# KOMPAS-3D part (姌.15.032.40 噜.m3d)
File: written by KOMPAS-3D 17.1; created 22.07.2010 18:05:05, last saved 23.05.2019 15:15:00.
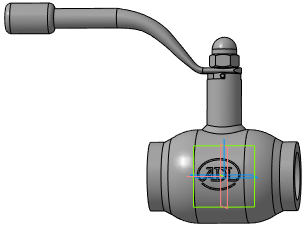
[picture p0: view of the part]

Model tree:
1. Плоскость XY
2. Плоскость ZX
3. Плоскость ZY
4. Ось X
5. Ось Y
6. Ось Z
7. Начало координат
8. Операция без истории:3  (labels: Сталь 20  ГОСТ 1050-88)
